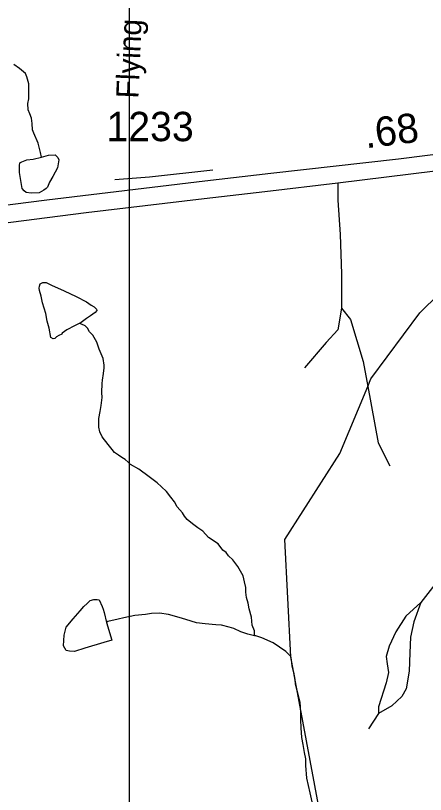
# Model space of a CAD drawing. Extents: x 2001466 to 2224147, y 644118 to 847247.
# Drawn here: x 2019988 to 2021734, y 722853 to 726170 of the extents above; entities that cross this region are included whole.
import ezdxf

# ---------------------------------------------------------------- set-up
doc = ezdxf.new("R2010")
doc.units = 0
for name, color, linetype in [('Exist Hydrographic Creek Single Shore', 7, 'Continuous'), ('Exist Hydrographic Misc Water Feature', 7, 'Continuous'), ('Exist Road Non-System Type 51', 7, 'Continuous'), ('Exist Road Non-System Type 51 Label', 7, 'Continuous'), ('Exist Road Primary US Divided Attributed', 7, 'Continuous'), ('Exist Road Primary US Mileage Hundredths English Label', 7, 'Continuous'), ('Exist Road Primary US Service Attributed', 7, 'Continuous'), ('Exist Road Secondary Type 51 Number Label', 7, 'Continuous'), ('Map Preparation Inset Cut Line', 7, 'Continuous')]:
    doc.layers.add(name, color=color, linetype=linetype)

msp = doc.modelspace()

# ---------------------------------------------------------------- linework, layer by layer
at = {"layer": 'Exist Hydrographic Creek Single Shore'}
for points in [[(2021488.6, 724591), (2021502.3, 724623.8), (2021710.2, 724904.9), (2022126.2, 725313.2), (2022309.4, 725381.6), (2022401.2, 725455.2), (2022443.3, 725674.2), (2022526.3, 725830), (2022642.4, 725932.6), (2023134.3, 726024.3)], [(2021286.1, 722429.8), (2021278.2, 722807.3), (2021161.3, 723439.6), (2021135.2, 723938.9), (2021369.2, 724304.9), (2021488.6, 724591)]]:
    msp.add_lwpolyline(points, dxfattribs=at)
at = {"layer": 'Exist Hydrographic Misc Water Feature'}
for points in [[(2020098.7, 725567.4), (2020094.6, 725587.4), (2020084.7, 725627.4), (2020066.5, 725669.4), (2020060.6, 725683.4), (2020058.5, 725711.4), (2020056.7, 725733.4), (2020048.7, 725751.3), (2020042.5, 725769.3), (2020040.7, 725795.3), (2020044.6, 725815.3), (2020044.6, 725829.4), (2020044.6, 725843.3), (2020044.6, 725859.3), (2020044.4, 725879.3), (2020036.4, 725909.3), (2020030.4, 725923.3), (2020004.4, 725945.3), (2019980.4, 725961.3)], [(2020098.7, 725567.4), (2020128.6, 725575.4), (2020156.7, 725577.4), (2020168.6, 725565.4), (2020172.7, 725555.4), (2020166.8, 725521.4), (2020146.7, 725485.4), (2020132.7, 725461.5), (2020124.7, 725439.4), (2020118.8, 725433.4), (2020108.7, 725427.4), (2020088.6, 725415.4), (2020054.8, 725413.4), (2020032.9, 725417.4), (2020024.9, 725423.4), (2020016.9, 725433.4), (2020004.8, 725501.4), (2020004.8, 725531.4), (2020006.6, 725543.4), (2020014.6, 725547.4), (2020036.8, 725555.4), (2020062.6, 725559.4), (2020098.7, 725567.4)], [(2020259, 724859.6), (2020238.9, 724849.6), (2020207, 724831.5), (2020187.1, 724817.5), (2020185, 724813.5), (2020173.1, 724807.5), (2020163.1, 724801.5), (2020155.1, 724795.5), (2020149.1, 724793.5), (2020139.1, 724799.5), (2020131.1, 724839.5), (2020123.1, 724869.5), (2020117.1, 724901.5), (2020103, 724947.4), (2020096.8, 724975.5), (2020090.9, 724999.4), (2020088.8, 725009.5), (2020090.9, 725017.5), (2020092.9, 725027.5), (2020104.8, 725033.4), (2020119, 725033.4), (2020140.9, 725021.5), (2020194.9, 724997.5), (2020246.9, 724973.5), (2020290.8, 724951.5), (2020310.9, 724937.5), (2020323, 724929.5), (2020333.1, 724919.6), (2020335.1, 724913.6), (2020327.1, 724905.6), (2020307, 724891.6), (2020291, 724879.6), (2020267, 724863.6), (2020259, 724859.6)], [(2021005.6, 723528.2), (2021005.6, 723550.2), (2020995.6, 723574.1), (2020993.5, 723608.1), (2020983.7, 723644.1), (2020979.6, 723668.1), (2020971.6, 723692.1), (2020969.5, 723714.2), (2020969.5, 723734.1), (2020963.6, 723758.1), (2020957.4, 723784.1), (2020935.5, 723824.1), (2020913.6, 723852.1), (2020895.5, 723870), (2020885.5, 723884), (2020871.5, 723894.1), (2020851.4, 723920.1), (2020809.6, 723948), (2020785.4, 723974), (2020765.3, 723988), (2020741.3, 724005.9), (2020719.4, 724023.9), (2020707.5, 724037.9), (2020699.5, 724051.9), (2020677.3, 724077.9), (2020665.5, 724099.9), (2020649.5, 724119.9), (2020631.4, 724143.9), (2020609.5, 724163.9), (2020591.4, 724179.9), (2020557.2, 724205.8), (2020513.3, 724237.8), (2020477.2, 724257.8), (2020467.4, 724267.7), (2020455.3, 724279.7), (2020441.3, 724287.7), (2020427.2, 724297.7), (2020409.3, 724309.7), (2020399.3, 724321.7), (2020383.3, 724343.7), (2020357.3, 724375.7), (2020347.2, 724397.7), (2020343.3, 724417.7), (2020343.3, 724453.7), (2020349.1, 724483.7), (2020353.2, 724509.7), (2020357.1, 724543.7), (2020355.2, 724565.6), (2020357.3, 724603.7), (2020359.1, 724617.7), (2020363.2, 724645.6), (2020365.3, 724669.6), (2020365.1, 724681.7), (2020361, 724709.6), (2020345, 724749.6), (2020335.1, 724779.6), (2020317.1, 724809.6), (2020303.1, 724823.5), (2020295.1, 724839.6), (2020285.1, 724849.6), (2020269.1, 724855.6), (2020259, 724859.6)], [(2020375.7, 723585.8), (2020397.7, 723509.8), (2020363.8, 723499.8), (2020283.9, 723475.7), (2020239.8, 723461.7), (2020217.8, 723463.7), (2020203.7, 723465.7), (2020191.8, 723485.7), (2020195.7, 723531.7), (2020203.7, 723565.7), (2020233.8, 723601.7), (2020263.8, 723635.7), (2020279.5, 723653.8), (2020293.7, 723665.8), (2020305.6, 723679.8), (2020321.6, 723683.8), (2020335.7, 723683.8), (2020343.7, 723681.8), (2020357.7, 723653.8), (2020361.6, 723641.8), (2020365.7, 723627.8), (2020375.7, 723585.8)], [(2021005.6, 723528.2), (2020977.5, 723536.2), (2020947.6, 723546.1), (2020917.7, 723560.1), (2020897.6, 723566.1), (2020865.6, 723574.1), (2020841.6, 723576.1), (2020795.7, 723580.1), (2020759.6, 723584), (2020713.6, 723598), (2020699.7, 723602), (2020665.7, 723611.9), (2020639.6, 723619.9), (2020601.7, 723625.9), (2020567.6, 723623.9), (2020541.6, 723619.9), (2020495.7, 723615.9), (2020449.5, 723605.8), (2020425.5, 723599.8), (2020381.7, 723589.8), (2020375.7, 723585.8)], [(2021159.6, 723442.3), (2021139.5, 723462.2), (2021085.6, 723498.2), (2021037.6, 723520.2), (2021011.6, 723528.1), (2021005.6, 723528.2)], [(2021159.6, 723442.3), (2021161.7, 723426.3), (2021165.8, 723400.3), (2021171.7, 723374.3), (2021177.7, 723342.3), (2021179.7, 723324.2), (2021185.7, 723302.3), (2021199.8, 723246.3), (2021201.7, 723202.3), (2021201.9, 723170.3), (2021203.9, 723136.3), (2021205.8, 723096.3), (2021211.9, 723066.4), (2021217.9, 723032.3), (2021223.8, 723004.4), (2021224, 722976.4), (2021227.9, 722922.4), (2021242.1, 722860.4), (2021256, 722796.4)]]:
    msp.add_lwpolyline(points, dxfattribs=at)
at = {"layer": 'Exist Road Non-System Type 51'}
for points in [[(2021360.5, 725457.5), (2021360.5, 725384.5), (2021371.1, 725237.4), (2021376.7, 725070.5), (2021376.7, 724924.4)], [(2021376.7, 724924.4), (2021360.5, 724832.4), (2021311.8, 724778.3), (2021219.8, 724670)], [(2021376.7, 724924.4), (2021414.6, 724875.7), (2021468.7, 724697.1), (2021488.6, 724591)], [(2021488.6, 724591), (2021533.6, 724350.7), (2021582.3, 724253.2)], [(2022191.2, 723505.6), (2022091.2, 723520), (2022056, 723543.5), (2022001.8, 723635.5), (2021900.1, 723730), (2021862.7, 723819.2), (2021829.6, 723817.7), (2021714.6, 723671)], [(2021714.6, 723671), (2021651.1, 723612.1), (2021608, 723545.9), (2021579.2, 723484.1), (2021566.3, 723440.9), (2021570.6, 723409.3), (2021576.4, 723371.9), (2021566.3, 723328.7), (2021534.7, 723226.6), (2021534.7, 723197.8)], [(2021714.6, 723671), (2021684.2, 723587.6), (2021671.2, 723522.9), (2021668.4, 723456.7), (2021665.5, 723377.6), (2021652.5, 723302.8), (2021633.9, 723269.7), (2021590.7, 723230.9), (2021534.7, 723197.8)], [(2021534.7, 723197.8), (2021491.6, 723133.1)]]:
    msp.add_lwpolyline(points, dxfattribs=at)
at = {"layer": 'Exist Road Primary US Divided Attributed'}
for points in [[(2022683.7, 725697.8), (2022012.2, 725607.8), (2021619, 725559.1), (2021075.9, 725497.1), (2020794.1, 725464.6), (2020121.2, 725383.5), (2019094.7, 725253)], [(2019103.3, 725179.4), (2020289.4, 725331.8), (2020791.1, 725390.8), (2021050.8, 725420.4), (2021360.5, 725457.5), (2022179.7, 725559.1), (2022689.6, 725625.5)]]:
    msp.add_lwpolyline(points, dxfattribs=at)
at = {"layer": 'Exist Road Primary US Service Attributed'}
msp.add_lwpolyline([(2020410.5, 725472.3), (2020558.4, 725484.1), (2020828.7, 725513.7)], dxfattribs=at)
at = {"layer": 'Map Preparation Inset Cut Line'}
for p, q in [((2020472.9, 725344.9), (2020472.9, 726933.7)), ((2020472.9, 720963.4), (2020472.9, 725344.9))]:
    msp.add_line(p, q, dxfattribs=at)

# ---------------------------------------------------------------- texts
at = {"layer": 'Exist Road Non-System Type 51 Label'}
msp.add_text('Flying', height=95, rotation=87.4988, dxfattribs=at).set_placement((2020511.2, 725815.7))
at = {"layer": 'Exist Road Primary US Mileage Hundredths English Label'}
msp.add_text('.68', height=125, rotation=7.0589, dxfattribs=at).set_placement((2021480.8, 725604.9))
at = {"layer": 'Exist Road Secondary Type 51 Number Label'}
msp.add_text('1233', height=125, dxfattribs=at).set_placement((2020375.4, 725635.4))

doc.saveas('drawing.dxf')
